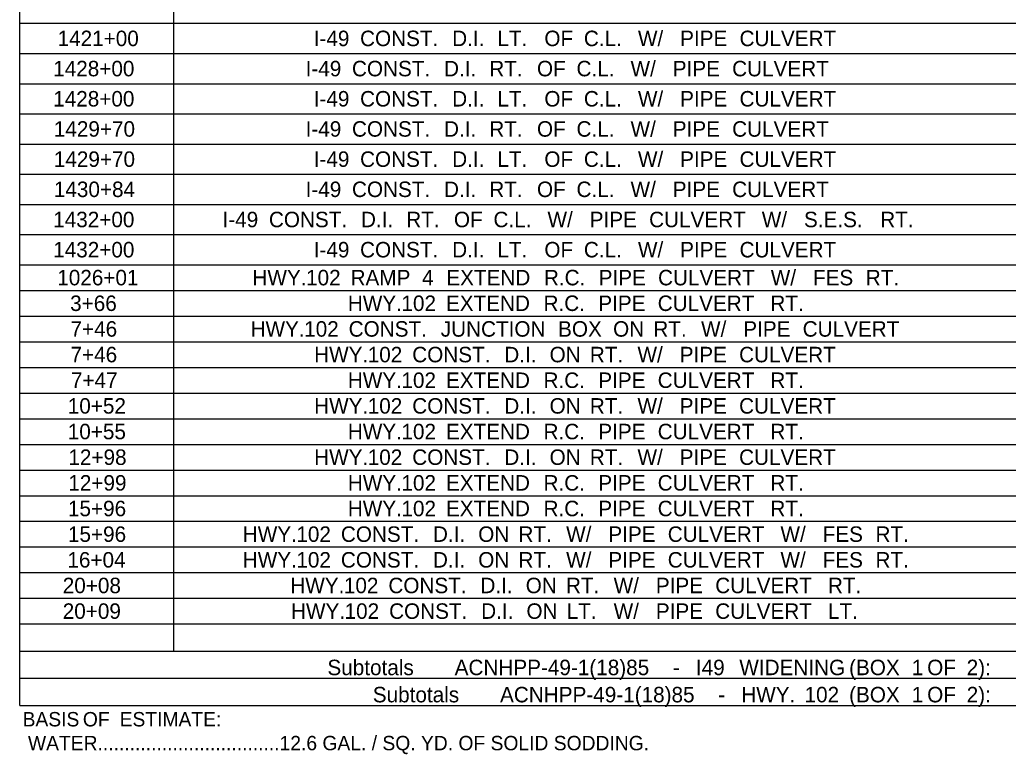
# Model space of a CAD drawing. Extents: x 1226564 to 1228153, y 151309 to 152340.
# Drawn here: x 1226563.6 to 1226835.5, y 151341 to 151543.2 of the extents above; entities that cross this region are included whole.
import ezdxf

# ---------------------------------------------------------------- set-up
doc = ezdxf.new("R2010")
doc.units = 0
doc.layers.add('R_Dimension', color=7, linetype='Continuous')

msp = doc.modelspace()

# ---------------------------------------------------------------- linework, layer by layer
at = {"layer": 'R_Dimension'}
for p, q in [((1226563.55, 151354.44), (1226563.55, 152160.49)), ((1226605.93, 151369.4), (1226605.93, 152160.49)), ((1226563.55, 151542.24), (1228152.75, 151542.24)), ((1226563.55, 151533.93), (1228152.75, 151533.93)), ((1226563.55, 151525.62), (1228152.75, 151525.62)), ((1226563.55, 151517.31), (1228152.75, 151517.31)), ((1226563.55, 151509), (1228152.75, 151509)), ((1226563.55, 151500.69), (1228152.75, 151500.69)), ((1226563.55, 151492.38), (1228152.75, 151492.38)), ((1226563.55, 151484.07), (1228152.75, 151484.07)), ((1226563.55, 151475.76), (1228152.75, 151475.76)), ((1226563.55, 151468.7), (1228152.75, 151468.7)), ((1226563.55, 151461.64), (1228152.75, 151461.64)), ((1226563.55, 151454.57), (1228152.75, 151454.57)), ((1226563.55, 151447.51), (1228152.75, 151447.51)), ((1226563.55, 151440.45), (1228152.75, 151440.45)), ((1226563.55, 151433.38), (1228152.75, 151433.38)), ((1226563.55, 151426.32), (1228152.75, 151426.32)), ((1226563.55, 151419.26), (1228152.75, 151419.26)), ((1226563.55, 151412.19), (1228152.75, 151412.19)), ((1226563.55, 151405.13), (1228152.75, 151405.13)), ((1226563.55, 151398.07), (1228152.75, 151398.07)), ((1226563.55, 151391), (1228152.75, 151391)), ((1226563.55, 151383.94), (1228152.75, 151383.94)), ((1226563.55, 151376.88), (1228152.75, 151376.88)), ((1226563.55, 151369.4), (1228152.75, 151369.4)), ((1226563.55, 151361.92), (1228152.75, 151361.92)), ((1226563.55, 151354.44), (1228152.75, 151354.44))]:
    msp.add_line(p, q, dxfattribs=at)

# ---------------------------------------------------------------- texts
for s, height, p in [('1421+00', 4.261, (1226573.96, 151535.96)), ('I-49', 4.261, (1226644.42, 151535.96)), (' CONST.', 4.261, (1226655.59, 151535.96)), (' D.I.', 4.261, (1226680.93, 151535.96)), (' LT.', 4.261, (1226693.37, 151535.96)), (' OF', 4.261, (1226706.29, 151535.96)), (' C.L.', 4.261, (1226717.16, 151535.96)), (' W/', 4.261, (1226732.03, 151535.96)), (' PIPE', 4.261, (1226743.64, 151535.96)), (' CULVERT', 4.261, (1226759.98, 151535.96)), ('1428+00', 4.261, (1226572.75, 151527.65)), ('I-49', 4.261, (1226642.19, 151527.65)), (' CONST.', 4.261, (1226653.36, 151527.65)), (' D.I.', 4.261, (1226678.69, 151527.65)), (' RT.', 4.261, (1226691.14, 151527.65)), (' OF', 4.261, (1226704.26, 151527.65)), (' C.L.', 4.261, (1226715.13, 151527.65)), (' W/', 4.261, (1226730, 151527.65)), (' PIPE', 4.261, (1226741.61, 151527.65)), (' CULVERT', 4.261, (1226757.95, 151527.65)), ('1428+00', 4.261, (1226572.75, 151519.34)), ('I-49', 4.261, (1226644.42, 151519.34)), (' CONST.', 4.261, (1226655.59, 151519.34)), (' D.I.', 4.261, (1226680.93, 151519.34)), (' LT.', 4.261, (1226693.37, 151519.34)), (' OF', 4.261, (1226706.29, 151519.34)), (' C.L.', 4.261, (1226717.16, 151519.34)), (' W/', 4.261, (1226732.03, 151519.34)), (' PIPE', 4.261, (1226743.64, 151519.34)), (' CULVERT', 4.261, (1226759.98, 151519.34)), ('1429+70', 4.261, (1226572.92, 151511.03)), ('I-49', 4.261, (1226642.19, 151511.03)), (' CONST.', 4.261, (1226653.36, 151511.03)), (' D.I.', 4.261, (1226678.69, 151511.03)), (' RT.', 4.261, (1226691.14, 151511.03)), (' OF', 4.261, (1226704.26, 151511.03)), (' C.L.', 4.261, (1226715.13, 151511.03)), (' W/', 4.261, (1226730, 151511.03)), (' PIPE', 4.261, (1226741.61, 151511.03)), (' CULVERT', 4.261, (1226757.95, 151511.03)), ('1429+70', 4.261, (1226572.92, 151502.72)), ('I-49', 4.261, (1226644.42, 151502.72)), (' CONST.', 4.261, (1226655.59, 151502.72)), (' D.I.', 4.261, (1226680.93, 151502.72)), (' LT.', 4.261, (1226693.37, 151502.72)), (' OF', 4.261, (1226706.29, 151502.72)), (' C.L.', 4.261, (1226717.16, 151502.72)), (' W/', 4.261, (1226732.03, 151502.72)), (' PIPE', 4.261, (1226743.64, 151502.72)), (' CULVERT', 4.261, (1226759.98, 151502.72)), ('1430+84', 4.261, (1226572.93, 151494.41)), ('I-49', 4.261, (1226642.19, 151494.41)), (' CONST.', 4.261, (1226653.36, 151494.41)), (' D.I.', 4.261, (1226678.69, 151494.41)), (' RT.', 4.261, (1226691.14, 151494.41)), (' OF', 4.261, (1226704.26, 151494.41)), (' C.L.', 4.261, (1226715.13, 151494.41)), (' W/', 4.261, (1226730, 151494.41)), (' PIPE', 4.261, (1226741.61, 151494.41)), (' CULVERT', 4.261, (1226757.95, 151494.41)), ('1432+00', 4.261, (1226572.75, 151486.1)), ('I-49', 4.261, (1226619.34, 151486.1)), (' CONST.', 4.261, (1226630.51, 151486.1)), (' D.I.', 4.261, (1226655.84, 151486.1)), (' RT.', 4.261, (1226668.29, 151486.1)), (' OF', 4.261, (1226681.41, 151486.1)), (' C.L.', 4.261, (1226692.28, 151486.1)), (' W/', 4.261, (1226707.15, 151486.1)), (' PIPE', 4.261, (1226718.76, 151486.1)), (' CULVERT', 4.261, (1226735.1, 151486.1)), (' W/', 4.261, (1226766.1, 151486.1)), (' S.E.S.', 4.261, (1226777.71, 151486.1)), (' RT.', 4.261, (1226798.69, 151486.1)), ('1432+00', 4.261, (1226572.75, 151477.79)), ('I-49', 4.261, (1226644.42, 151477.79)), (' CONST.', 4.261, (1226655.59, 151477.79)), (' D.I.', 4.261, (1226680.93, 151477.79)), (' LT.', 4.261, (1226693.37, 151477.79)), (' OF', 4.261, (1226706.29, 151477.79)), (' C.L.', 4.261, (1226717.16, 151477.79)), (' W/', 4.261, (1226732.03, 151477.79)), (' PIPE', 4.261, (1226743.64, 151477.79)), (' CULVERT', 4.261, (1226759.98, 151477.79)), ('1026+01', 4.261, (1226573.87, 151470.1)), ('HWY.', 4.261, (1226627.57, 151470.1)), (' 102', 4.261, (1226640.73, 151470.1)), (' RAMP', 4.261, (1226652.97, 151470.1)), (' 4', 4.261, (1226672.64, 151470.1)), (' EXTEND', 4.261, (1226679.31, 151470.1)), (' R.C.', 4.261, (1226706.16, 151470.1)), (' PIPE', 4.261, (1226721.22, 151470.1)), (' CULVERT', 4.261, (1226737.57, 151470.1)), (' W/', 4.261, (1226768.57, 151470.1)), (' FES', 4.261, (1226780.18, 151470.1)), (' RT.', 4.261, (1226794.71, 151470.1)), ('3+66', 4.261, (1226577.41, 151463.04)), ('HWY.', 4.261, (1226653.81, 151463.04)), (' 102', 4.261, (1226666.97, 151463.04)), (' EXTEND', 4.261, (1226679.21, 151463.04)), (' R.C.', 4.261, (1226706.06, 151463.04)), (' PIPE', 4.261, (1226721.12, 151463.04)), (' CULVERT', 4.261, (1226737.47, 151463.04)), (' RT.', 4.261, (1226768.47, 151463.04)), ('7+46', 4.261, (1226577.51, 151455.97)), ('HWY.', 4.261, (1226627.05, 151455.97)), (' 102', 4.261, (1226640.21, 151455.97)), (' CONST.', 4.261, (1226652.45, 151455.97)), (' JUNCTION', 4.261, (1226677.79, 151455.97)), (' BOX', 4.261, (1226710.07, 151455.97)), (' ON', 4.261, (1226725.2, 151455.97)), (' RT.', 4.261, (1226736.27, 151455.97)), (' W/', 4.261, (1226749.39, 151455.97)), (' PIPE', 4.261, (1226761, 151455.97)), (' CULVERT', 4.261, (1226777.35, 151455.97)), ('7+46', 4.261, (1226577.51, 151448.91)), ('HWY.', 4.261, (1226644.54, 151448.91)), (' 102', 4.261, (1226657.69, 151448.91)), (' CONST.', 4.261, (1226669.94, 151448.91)), (' D.I.', 4.261, (1226695.27, 151448.91)), (' ON', 4.261, (1226707.72, 151448.91)), (' RT.', 4.261, (1226718.79, 151448.91)), (' W/', 4.261, (1226731.91, 151448.91)), (' PIPE', 4.261, (1226743.52, 151448.91)), (' CULVERT', 4.261, (1226759.86, 151448.91)), ('7+47', 4.261, (1226577.63, 151441.85)), ('HWY.', 4.261, (1226653.81, 151441.85)), (' 102', 4.261, (1226666.97, 151441.85)), (' EXTEND', 4.261, (1226679.21, 151441.85)), (' R.C.', 4.261, (1226706.06, 151441.85)), (' PIPE', 4.261, (1226721.12, 151441.85)), (' CULVERT', 4.261, (1226737.47, 151441.85)), (' RT.', 4.261, (1226768.47, 151441.85)), ('10+52', 4.261, (1226576.76, 151434.78)), ('HWY.', 4.261, (1226644.54, 151434.78)), (' 102', 4.261, (1226657.69, 151434.78)), (' CONST.', 4.261, (1226669.94, 151434.78)), (' D.I.', 4.261, (1226695.27, 151434.78)), (' ON', 4.261, (1226707.72, 151434.78)), (' RT.', 4.261, (1226718.79, 151434.78)), (' W/', 4.261, (1226731.91, 151434.78)), (' PIPE', 4.261, (1226743.52, 151434.78)), (' CULVERT', 4.261, (1226759.86, 151434.78)), ('10+55', 4.261, (1226576.76, 151427.72)), ('HWY.', 4.261, (1226653.81, 151427.72)), (' 102', 4.261, (1226666.97, 151427.72)), (' EXTEND', 4.261, (1226679.21, 151427.72)), (' R.C.', 4.261, (1226706.06, 151427.72)), (' PIPE', 4.261, (1226721.12, 151427.72)), (' CULVERT', 4.261, (1226737.47, 151427.72)), (' RT.', 4.261, (1226768.47, 151427.72)), ('12+98', 4.261, (1226576.93, 151420.66)), ('HWY.', 4.261, (1226644.54, 151420.66)), (' 102', 4.261, (1226657.69, 151420.66)), (' CONST.', 4.261, (1226669.94, 151420.66)), (' D.I.', 4.261, (1226695.27, 151420.66)), (' ON', 4.261, (1226707.72, 151420.66)), (' RT.', 4.261, (1226718.79, 151420.66)), (' W/', 4.261, (1226731.91, 151420.66)), (' PIPE', 4.261, (1226743.52, 151420.66)), (' CULVERT', 4.261, (1226759.86, 151420.66)), ('12+99', 4.261, (1226576.91, 151413.59)), ('HWY.', 4.261, (1226653.81, 151413.59)), (' 102', 4.261, (1226666.97, 151413.59)), (' EXTEND', 4.261, (1226679.21, 151413.59)), (' R.C.', 4.261, (1226706.06, 151413.59)), (' PIPE', 4.261, (1226721.12, 151413.59)), (' CULVERT', 4.261, (1226737.47, 151413.59)), (' RT.', 4.261, (1226768.47, 151413.59)), ('15+96', 4.261, (1226576.81, 151406.53)), ('HWY.', 4.261, (1226653.81, 151406.53)), (' 102', 4.261, (1226666.97, 151406.53)), (' EXTEND', 4.261, (1226679.21, 151406.53)), (' R.C.', 4.261, (1226706.06, 151406.53)), (' PIPE', 4.261, (1226721.12, 151406.53)), (' CULVERT', 4.261, (1226737.47, 151406.53)), (' RT.', 4.261, (1226768.47, 151406.53)), ('15+96', 4.261, (1226576.81, 151399.47)), ('HWY.', 4.261, (1226624.91, 151399.47)), (' 102', 4.261, (1226638.06, 151399.47)), (' CONST.', 4.261, (1226650.31, 151399.47)), (' D.I.', 4.261, (1226675.64, 151399.47)), (' ON', 4.261, (1226688.09, 151399.47)), (' RT.', 4.261, (1226699.16, 151399.47)), (' W/', 4.261, (1226712.28, 151399.47)), (' PIPE', 4.261, (1226723.89, 151399.47)), (' CULVERT', 4.261, (1226740.23, 151399.47)), (' W/', 4.261, (1226771.24, 151399.47)), (' FES', 4.261, (1226782.85, 151399.47)), (' RT.', 4.261, (1226797.38, 151399.47)), (' W/', 4.261, (1226712.28, 151392.4)), (' W/', 4.261, (1226771.24, 151392.4)), ('16+04', 4.261, (1226576.66, 151392.4)), ('HWY.', 4.261, (1226624.91, 151392.4)), (' 102', 4.261, (1226638.06, 151392.4)), (' CONST.', 4.261, (1226650.31, 151392.4)), (' D.I.', 4.261, (1226675.64, 151392.4)), (' ON', 4.261, (1226688.09, 151392.4)), (' RT.', 4.261, (1226699.16, 151392.4)), (' PIPE', 4.261, (1226723.89, 151392.4)), (' CULVERT', 4.261, (1226740.23, 151392.4)), (' FES', 4.261, (1226782.85, 151392.4)), (' RT.', 4.261, (1226797.38, 151392.4)), ('20+08', 4.261, (1226575.38, 151385.34)), ('HWY.', 4.261, (1226637.98, 151385.34)), (' 102', 4.261, (1226651.13, 151385.34)), (' CONST.', 4.261, (1226663.38, 151385.34)), (' D.I.', 4.261, (1226688.71, 151385.34)), (' ON', 4.261, (1226701.16, 151385.34)), (' RT.', 4.261, (1226712.23, 151385.34)), (' W/', 4.261, (1226725.35, 151385.34)), (' PIPE', 4.261, (1226736.96, 151385.34)), (' CULVERT', 4.261, (1226753.3, 151385.34)), (' RT.', 4.261, (1226784.31, 151385.34)), ('20+09', 4.261, (1226575.37, 151378.28)), ('HWY.', 4.261, (1226638.18, 151378.28)), (' 102', 4.261, (1226651.33, 151378.28)), (' CONST.', 4.261, (1226663.58, 151378.28)), (' D.I.', 4.261, (1226688.91, 151378.28)), (' ON', 4.261, (1226701.36, 151378.28)), (' LT.', 4.261, (1226712.43, 151378.28)), (' W/', 4.261, (1226725.35, 151378.28)), (' PIPE', 4.261, (1226736.96, 151378.28)), (' CULVERT', 4.261, (1226753.3, 151378.28)), (' LT.', 4.261, (1226784.31, 151378.28)), ('Subtotals', 4.261, (1226648.19, 151362.77)), (' ACNHPP-49-1(18)85', 4.2615, (1226681.61, 151362.77)), (' I49', 4.261, (1226747.98, 151362.77)), (' WIDENING', 4.261, (1226759.92, 151362.77)), (' (BOX', 4.261, (1226790.12, 151362.77)), (' 1', 4.261, (1226807.34, 151362.77)), (' OF', 4.261, (1226811.6, 151362.77)), (' 2):', 4.261, (1226822.47, 151362.77)), (' -', 4.261, (1226741.64, 151362.77)), ('Subtotals', 4.261, (1226660.67, 151355.29)), (' ACNHPP-49-1(18)85', 4.2615, (1226694.09, 151355.29)), (' HWY.', 4.261, (1226760.46, 151355.29)), (' 102', 4.261, (1226777.87, 151355.29)), (' (BOX', 4.261, (1226790.12, 151355.29)), (' 1', 4.261, (1226807.34, 151355.29)), (' OF', 4.261, (1226811.6, 151355.29)), (' 2):', 4.261, (1226822.47, 151355.29)), (' -', 4.261, (1226754.12, 151355.29)), ('BASIS', 3.965, (1226564.33, 151348.66)), (' OF', 3.965, (1226579.44, 151348.66)), (' ESTIMATE:', 3.965, (1226589.55, 151348.66)), (' WATER..................................12.6 GAL. / SQ. YD. OF SOLID SODDING.', 3.9647, (1226564.33, 151342.09))]:
    msp.add_text(s, height=height, dxfattribs=at).set_placement(p)

doc.saveas('drawing.dxf')
